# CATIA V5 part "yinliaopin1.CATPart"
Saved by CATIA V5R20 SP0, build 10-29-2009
Part number: Part1
Material "China Blue": density 7860 kg/m3, Young's modulus 2e+11 Pa, Poisson ratio 0.266
Bounding box of the stored display mesh (mm): x -25 to 25, y -25 to 25.2, z 0 to 110
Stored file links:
  C:\Users\Lenovo\Desktop\yinliaopin1.CATPart
  F:\catia\win_b64\startup\materials\Catalog.CATMaterial
  F:\catia\win_b64\startup\materials\sunset.jpg
  F:\catia\win_b64\startup\materials\yellow_env_512x512.jpg
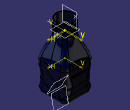
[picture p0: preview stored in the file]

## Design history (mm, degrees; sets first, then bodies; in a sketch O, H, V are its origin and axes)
Set1
  Sketch1 on face of Pad1 from Sketch3.L1, origin (25, 0, 0), H (0, 1, 0), V (0, 0, 1)
    spline S1 through (-40, 10) (-10, 20) (10, 10) (30, 20)
  Extrude1: Element1 Sketch1, Lim1 66, Lim2 66
  MultiSel1: CommonCtxFeats ({extract ExtractElem face of Fillet1}; {extract ExtractElem face of Pad1 from Sketch3.L1}; {extract ExtractElem face of Fillet1}; {extract ExtractElem face of Pad1 from Sketch3.L4}; {extract ExtractElem face of Fillet1}; {extract ExtractElem face of Pad1 from Sketch3.L3}; {extract ExtractElem face of Fillet1}; {extract ExtractElem face of Pad1 from Sketch3.L2})
  Sketch2 on face of Pad1 from Sketch3.L3, origin (-25, 0, 0), H (0, -1, 0), V (0, 0, 1)
    spline S1 through (-40, 20) (-10, 30) (10, 40) (30, 40)
  Extrude2: Element1 Sketch2, Lim1 66, Lim2 66
  MultiSel2: CommonCtxFeats ({extract ExtractElem face of Fillet1}; {extract ExtractElem face of Pad1 from Sketch3.L2}; {extract ExtractElem face of Fillet1}; {extract ExtractElem face of Pad1 from Sketch3.L1}; {extract ExtractElem face of Fillet1}; {extract ExtractElem face of Pad1 from Sketch3.L4}; {extract ExtractElem face of Fillet1}; {extract ExtractElem face of Pad1 from Sketch3.L3})
  Join1: Elements ({intersect ToIntersect1 {extract ExtractElem face of Fillet1}, ToIntersect2 Extrude2}; {intersect ToIntersect1 {extract ExtractElem face of Pad1 from Sketch3.L2}, ToIntersect2 Extrude2}; {intersect ToIntersect1 {extract ExtractElem face of Fillet1}, ToIntersect2 Extrude2}; {intersect ToIntersect1 {extract ExtractElem face of Pad1 from Sketch3.L1}, ToIntersect2 Extrude2}; {intersect ToIntersect1 {extract ExtractElem face of Fillet1}, ToIntersect2 Extrude2}; {intersect ToIntersect1 {extract ExtractElem face of Pad1 from Sketch3.L4}, ToIntersect2 Extrude2}; {intersect ToIntersect1 {extract ExtractElem face of Fillet1}, ToIntersect2 Extrude2}; {intersect ToIntersect1 {extract ExtractElem face of Pad1 from Sketch3.L3}, ToIntersect2 Extrude2})
  Join2: Elements ({intersect ToIntersect1 {extract ExtractElem face of Fillet1}, ToIntersect2 Extrude1}; {intersect ToIntersect1 {extract ExtractElem face of Pad1 from Sketch3.L1}, ToIntersect2 Extrude1}; {intersect ToIntersect1 {extract ExtractElem face of Fillet1}, ToIntersect2 Extrude1}; {intersect ToIntersect1 {extract ExtractElem face of Pad1 from Sketch3.L4}, ToIntersect2 Extrude1}; {intersect ToIntersect1 {extract ExtractElem face of Fillet1}, ToIntersect2 Extrude1}; {intersect ToIntersect1 {extract ExtractElem face of Pad1 from Sketch3.L3}, ToIntersect2 Extrude1}; {intersect ToIntersect1 {extract ExtractElem face of Fillet1}, ToIntersect2 Extrude1}; {intersect ToIntersect1 {extract ExtractElem face of Pad1 from Sketch3.L2}, ToIntersect2 Extrude1})
  Plane1: type Normal, Curve Join1, RefPoint vertex [face of MultiSel2 | face of MultiSel2]
  Circle1: type CtrRad, Start 0, End 180, Center vertex [face of MultiSel2 | face of MultiSel2], Support Plane1, Radius 1, FirstDirection (1, 0, 0)
  Plane2: type Normal, Curve Join2, RefPoint vertex [face of MultiSel1 | face of MultiSel1]
  Circle2: type CtrRad, Start 0, End 180, Center vertex [face of MultiSel1 | face of MultiSel1], Support Plane2, Radius 1, FirstDirection (1, 0, 0)
Body1 (main body), material "China Blue"
  Set2
    Sketch3 on xy-plane, origin (0, 0, 0), H (1, 0, 0), V (0, 1, 0)
      line L1 (25, 25) -> (25, -25)
      line L2 (25, -25) -> (-25, -25)
      line L3 (-25, -25) -> (-25, 25)
      line L4 (-25, 25) -> (25, 25)
      distance L2 L4 = 50
      distance L1 L3 = 50
      vertical: L1 V, L3 V
      horizontal: L2 H, L4 H
      equidistance: L1 L3 O, L2 L4 O
  Pad1: profile Sketch3, direction (0, 0, 1), length 50
  Fillet1: on edge [face of Pad1 from Sketch3.L2 | face of Pad1 from Sketch3.L3]; edge [face of Pad1 from Sketch3.L4 | face of Pad1 from Sketch3.L1]; edge [face of Pad1 from Sketch3.L3 | face of Pad1 from Sketch3.L4]; edge [face of Pad1 from Sketch3.L1 | face of Pad1 from Sketch3.L2]
  Fillet2: on edge [start face of Pad1 | face of Pad1 from Sketch3.L4]
  Plane3: type Offset, RefPlane end face of Pad1, Offset 40, reversed
  Sketch4 on Plane3, origin (0, 0, 90), H (1, 0, 0), V (0, -1, 0)
    circle A1 centre (0, 0) radius 15
    radius A1 = 15
  Pad2: profile Sketch4, direction (0, 0, -1), length -20
  Sketch5 on end face of Pad1, origin (0, 0, 50), H (1, 0, 0), V (0, 1, 0)
    point P1 (25, 0)
    distance V P1 = 25
    coincidence: P1 H
  Sketch6 on start face of Pad2, origin (0, 0, 90), H (1, 0, 0), V (0, -1, 0)
    point P1 (15, 0)
    distance P1 V = 15
    coincidence: P1 H
  Loft1: solid, Sections ({boundary Boundary {extract ExtractElem end face of Pad1}}; {boundary Boundary {extract ExtractElem start face of Pad2}}), StartFace end face of Pad1, EndFace start face of Pad2
  Slot1: profile Circle1, centre curve Join1
  Slot2: profile Circle2, centre curve Join2
  Shell1: IntOffset 1, Face end face of Pad2, ExtOffset 0
  Sketch7 on {extract ExtractElem start face of Pad2}, origin (0, 0, 90), H (1, 0, 0), V (0, 1, 0)
    point P1 (15, 0)
    distance P1 V = 15
    coincidence: P1 H
  Plane4: type Offset, RefPlane {extract ExtractElem start face of Pad2}, Offset 2
  Sketch8 on Plane4, origin (0, 0, 92), H (1, 0, 0), V (0, 1, 0)
    point P1 (15, 0)
    distance P1 V = 15
    coincidence: P1 H
  Helix1: Direction Z axis, RefPoint Sketch8, Pitch 2, Height 15, TaperAngle 0
  Point1: type OnCurve, Support Helix1, RefPoint vertex of Helix1, Length -3.889
  Line1: type PtDir, RefPoint vertex of Helix1, Direction (1, 0, 0), Start 0, End 7
  Connect1: Curve1 Helix1, Point1 Point1, Tension1 1, Curve2 Line1, Point2 vertex of Line1, Tension2 1
  Line2: type PtDir, RefPoint Sketch8, Direction (1, 0, 0), Start 0, End -7
  Point2: type OnCurve, Support Connect1, Length 5.227
  Connect2: Curve1 Line2, Point1 vertex of Line2, Tension1 1, Curve2 Connect1, Point2 Point2, Tension2 1
  Plane5: type Normal, Curve Connect2, RefPoint vertex of Connect1
  Sketch9 on Plane5, origin (-8, 0, 0), H (0, 1, 0), V (0, 0, 1)
    circle A1 centre (0, 107.0454) radius 0.5
    point P1 (0, 107.0454)
    coincidence: P1 V
  Rib1: profile Sketch9, centre curve Connect2
  Body2
    Sketch10 on face of Pad1 from Sketch3.L4, origin (0, 25, 0), H (-1, 0, 0), V (0, 0, 1)
      polyline C1
      polyline C2
      polyline C3
      polyline C4
      polyline C5
      polyline C6
      polyline C7
      polyline C8
      polyline C9
      polyline C10
      polyline C11
    Sketch11 on {extract ExtractElem start face of Pad2}, origin (0, 0, 90), H (1, 0, 0), V (0, 1, 0)
      circle A1 centre (0, 0) radius 14
      radius A1 = 14
    Pad3: profile Sketch11, direction (0, 0, 1), length 20
  Remove1: tool Body2
  Pad4: profile Sketch10, direction (0, 1, 0), length 0.2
